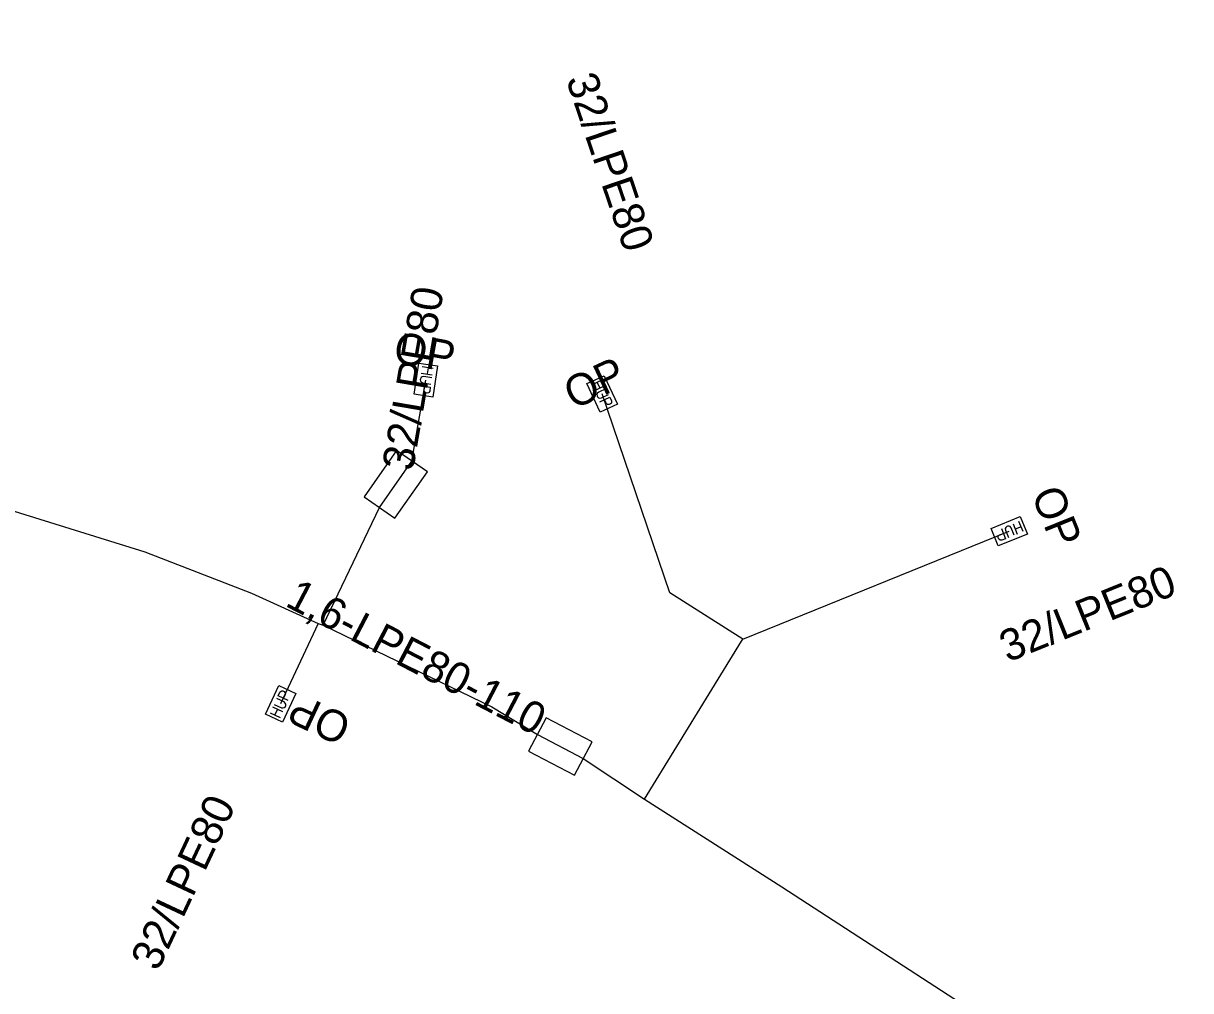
# Model space of a CAD drawing. Extents: x -762509 to -761250, y -1153000 to -1152256.
# Drawn here: x -761373.32 to -761336.19, y -1152558.65 to -1152527.87 of the extents above; entities that cross this region are included whole.
import ezdxf

# ---------------------------------------------------------------- set-up
doc = ezdxf.new("R2010")
doc.units = 0
for name, color, linetype in [('Vrstva 21', 7, 'Continuous'), ('Vrstva 29', 7, 'Continuous'), ('Vrstva 31', 7, 'Continuous'), ('Vrstva 32', 7, 'Continuous')]:
    doc.layers.add(name, color=color, linetype=linetype)

msp = doc.modelspace()

# ---------------------------------------------------------------- linework, layer by layer
at = {"layer": 'Vrstva 21'}
msp.add_lwpolyline([(-761456.83, -1152527.87), (-761448.25, -1152529.25), (-761446.58, -1152529.57), (-761444.73, -1152529.87), (-761425.09, -1152533.35), (-761412.86, -1152535.83), (-761404.73, -1152537.14), (-761396.67, -1152538.6), (-761395, -1152538.89), (-761392.98, -1152539.26), (-761384.89, -1152540.72), (-761378.87, -1152541.76), (-761369.46, -1152544.68), (-761366.06, -1152546), (-761363.94, -1152546.96), (-761363.78, -1152547.02), (-761358.42, -1152549.62), (-761356.97, -1152550.5), (-761355.51, -1152551.26), (-761353.56, -1152552.55), (-761349.19, -1152555.34), (-761336.19, -1152563.79)], dxfattribs=at)
at = {"layer": 'Vrstva 29'}
for points in [[(-761361.5, -1152543.61), (-761360.47, -1152542.14), (-761361.45, -1152541.46), (-761362.48, -1152542.93)], [(-761357.25, -1152551.03), (-761355.79, -1152551.79), (-761355.23, -1152550.73), (-761356.69, -1152549.97)]]:
    msp.add_lwpolyline(points, close=True, dxfattribs=at)
at = {"layer": 'Vrstva 31'}
for points in [[(-761363.78, -1152547.02), (-761361.99, -1152543.27), (-761360.96, -1152541.8), (-761360.52, -1152539.22)], [(-761350.44, -1152547.46), (-761352.76, -1152545.99), (-761354.91, -1152539.66)], [(-761350.48, -1152547.53), (-761350.44, -1152547.46), (-761341.96, -1152544.03)], [(-761363.94, -1152546.96), (-761365.14, -1152549.52)], [(-761353.56, -1152552.55), (-761350.48, -1152547.53)]]:
    msp.add_lwpolyline(points, dxfattribs=at)
at = {"layer": 'Vrstva 32'}
for p, q in [((-761360.663, -1152538.998), (-761360.317, -1152539.05)), ((-761360.287, -1152538.851), (-761360.633, -1152538.799)), ((-761360.45, -1152538.826), (-761360.48, -1152539.025)), ((-761354.921, -1152539.224), (-761355.238, -1152539.372)), ((-761355.07, -1152539.294), (-761354.985, -1152539.476)), ((-761360.723, -1152539.392), (-761360.377, -1152539.444)), ((-761355.153, -1152539.554), (-761354.836, -1152539.406)), ((-761354.984, -1152539.916), (-761354.667, -1152539.768)), ((-761341.84, -1152543.794), (-761341.71, -1152544.118)), ((-761341.523, -1152544.043), (-761341.654, -1152543.718)), ((-761342.21, -1152543.943), (-761342.08, -1152544.268)), ((-761341.585, -1152543.89), (-761341.771, -1152543.965)), ((-761364.897, -1152549.414), (-761365.214, -1152549.265)), ((-761365.066, -1152549.775), (-761365.383, -1152549.626)), ((-761365.319, -1152549.878), (-761365.234, -1152549.696)), ((-761365.469, -1152549.808), (-761365.152, -1152549.957))]:
    msp.add_line(p, q, dxfattribs=at)
for points in [[(-761360.149, -1152538.771), (-761360.298, -1152539.76), (-761360.891, -1152539.67), (-761360.742, -1152538.681), (-761360.149, -1152538.771)], [(-761360.332, -1152539.148), (-761360.58, -1152539.11), (-761360.631, -1152539.117), (-761360.668, -1152539.143), (-761360.691, -1152539.182), (-761360.695, -1152539.21), (-761360.685, -1152539.254), (-761360.656, -1152539.288), (-761360.61, -1152539.309), (-761360.362, -1152539.346)], [(-761354.85, -1152539.08), (-761354.427, -1152539.987), (-761354.971, -1152540.24), (-761355.393, -1152539.334), (-761354.85, -1152539.08)], [(-761360.377, -1152539.444), (-761360.396, -1152539.573), (-761360.419, -1152539.612), (-761360.437, -1152539.624), (-761360.472, -1152539.633), (-761360.521, -1152539.626), (-761360.552, -1152539.607), (-761360.565, -1152539.59), (-761360.576, -1152539.546), (-761360.557, -1152539.417)], [(-761354.794, -1152539.496), (-761355.021, -1152539.602), (-761355.06, -1152539.635), (-761355.077, -1152539.677), (-761355.074, -1152539.723), (-761355.062, -1152539.749), (-761355.029, -1152539.78), (-761354.987, -1152539.792), (-761354.936, -1152539.784), (-761354.709, -1152539.678)], [(-761354.667, -1152539.768), (-761354.612, -1152539.885), (-761354.61, -1152539.931), (-761354.618, -1152539.951), (-761354.642, -1152539.978), (-761354.687, -1152539.999), (-761354.723, -1152540), (-761354.744, -1152539.993), (-761354.777, -1152539.962), (-761354.832, -1152539.845)], [(-761341.384, -1152544.121), (-761342.311, -1152544.496), (-761342.535, -1152543.939), (-761341.608, -1152543.565), (-761341.384, -1152544.121)], [(-761342.08, -1152544.268), (-761342.2, -1152544.316), (-761342.245, -1152544.316), (-761342.265, -1152544.307), (-761342.291, -1152544.282), (-761342.309, -1152544.235), (-761342.309, -1152544.199), (-761342.301, -1152544.179), (-761342.268, -1152544.147), (-761342.148, -1152544.099)], [(-761341.801, -1152544.155), (-761341.895, -1152543.923), (-761341.927, -1152543.882), (-761341.968, -1152543.863), (-761342.013, -1152543.863), (-761342.04, -1152543.874), (-761342.072, -1152543.906), (-761342.087, -1152543.947), (-761342.082, -1152543.998), (-761341.988, -1152544.231)], [(-761365.624, -1152549.846), (-761365.2, -1152548.94), (-761364.657, -1152549.195), (-761365.081, -1152550.1), (-761365.624, -1152549.846)], [(-761365.341, -1152549.537), (-761365.114, -1152549.643), (-761365.064, -1152549.651), (-761365.021, -1152549.637), (-761364.987, -1152549.606), (-761364.975, -1152549.58), (-761364.973, -1152549.535), (-761364.99, -1152549.495), (-761365.029, -1152549.461), (-761365.256, -1152549.355)], [(-761365.214, -1152549.265), (-761365.159, -1152549.147), (-761365.126, -1152549.116), (-761365.105, -1152549.11), (-761365.069, -1152549.111), (-761365.024, -1152549.132), (-761365, -1152549.159), (-761364.992, -1152549.179), (-761364.994, -1152549.225), (-761365.049, -1152549.342)]]:
    msp.add_lwpolyline(points, dxfattribs=at)

# ---------------------------------------------------------------- texts
at = {"layer": 'Vrstva 29'}
msp.add_text('1,6-LPE80-110', height=1, rotation=332.5009, dxfattribs=at).set_placement((-761365.03, -1152546.39))
at = {"layer": 'Vrstva 31'}
for rotation, p in [(288.7602, (-761356.07, -1152529.65)), (288.7602, (-761356.07, -1152529.65)), (80.3217, (-761360.93, -1152542.14)), (80.3217, (-761360.93, -1152542.14)), (22.0224, (-761342.01, -1152548.21)), (22.0224, (-761342.01, -1152548.21)), (64.8852, (-761369.04, -1152558.06)), (64.8852, (-761369.04, -1152558.06))]:
    msp.add_text('32/LPE80', height=1, rotation=rotation, dxfattribs=at).set_placement(p)
at = {"layer": 'Vrstva 32'}
for rotation, p in [(349.7406, (-761361.59, -1152538.65)), (349.7406, (-761361.59, -1152538.65)), (25.0075, (-761355.82, -1152540.17)), (25.0075, (-761355.82, -1152540.17)), (291.9793, (-761341.27, -1152542.85)), (291.9793, (-761341.27, -1152542.85)), (154.8852, (-761362.82, -1152549.97)), (154.8852, (-761362.82, -1152549.97))]:
    msp.add_text('OP', height=1, rotation=rotation, dxfattribs=at).set_placement(p)

doc.saveas('drawing.dxf')
